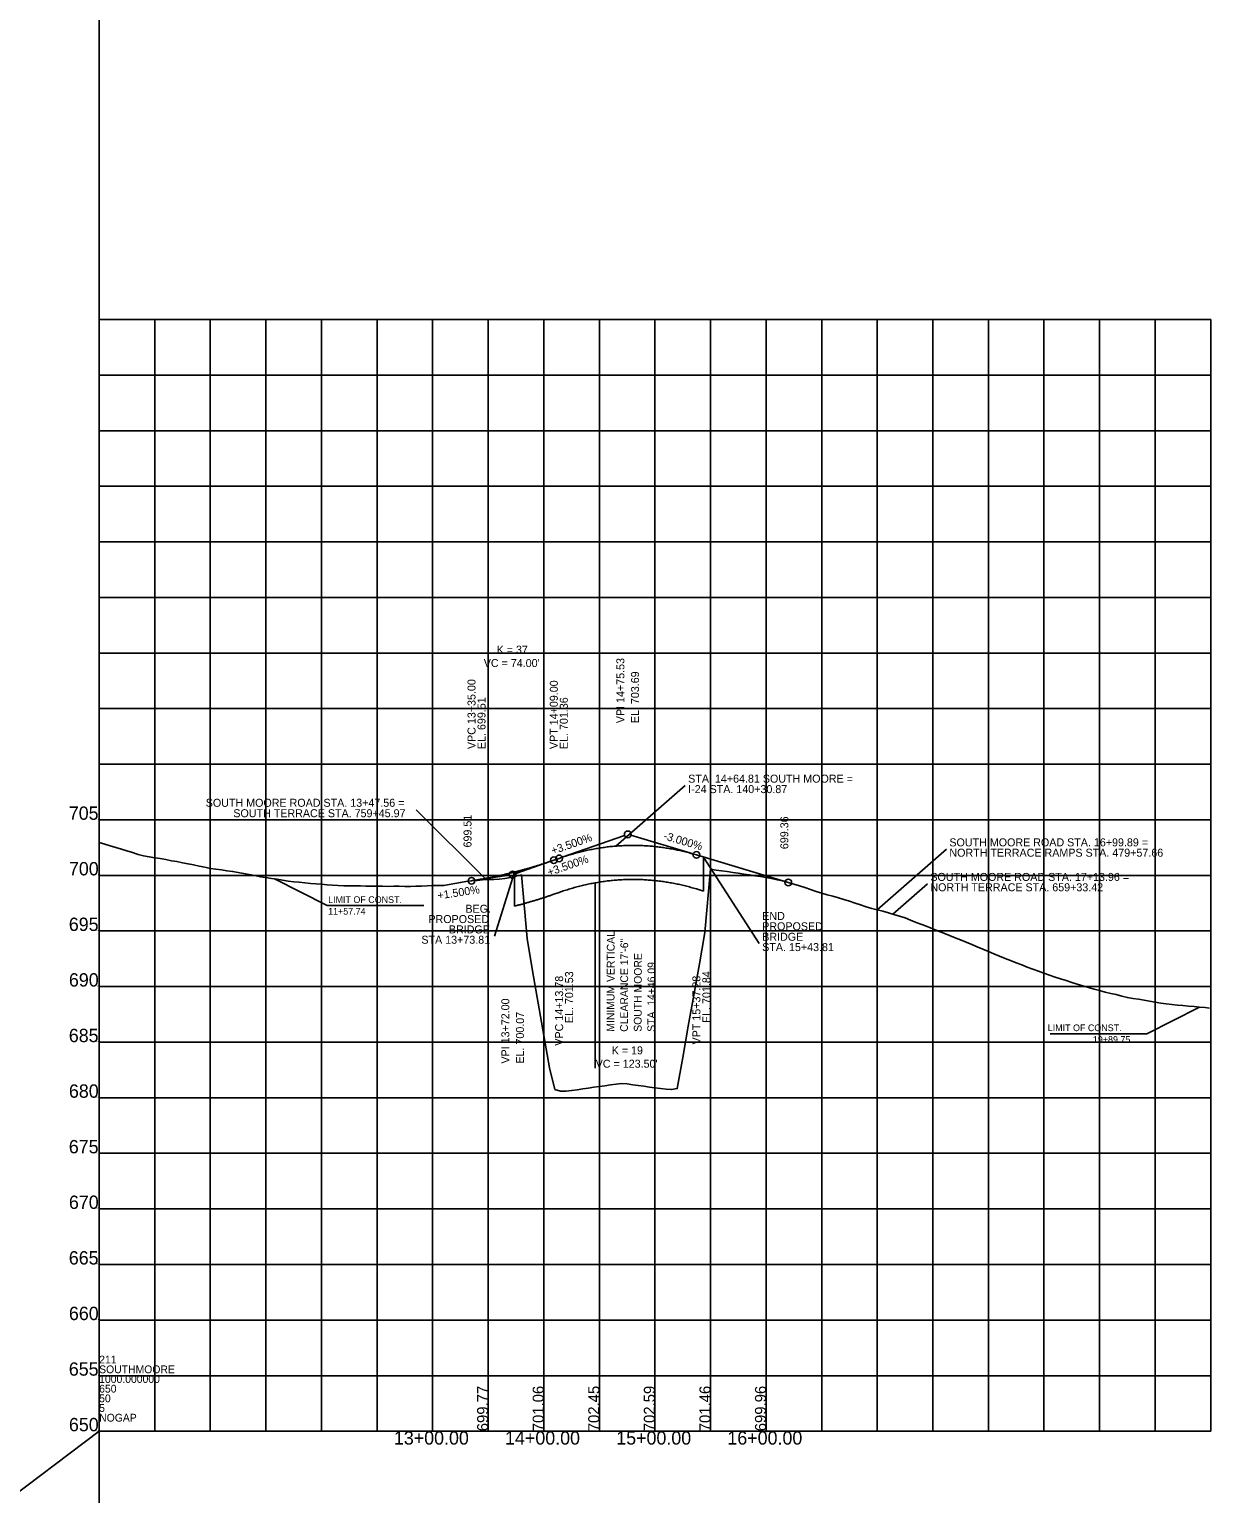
# Model space of a CAD drawing. Extents: x -7164 to 2214450, y -19642 to 253469.
# Drawn here: x -63 to 1000, y -6056 to -4739 of the extents above; entities that cross this region are included whole.
import ezdxf

# ---------------------------------------------------------------- set-up
doc = ezdxf.new("R2010")
doc.units = 0
for name, color, linetype in [('DESIGN - PROFILE - Proposed', 7, 'Continuous'), ('DESIGN - PROFILE - Proposed Curve Text', 7, 'Continuous'), ('DESIGN - PROFILE - Proposed Text', 7, 'Continuous'), ('DESIGN - SCRATCH - User 1', 7, 'Continuous'), ('DESIGN - SHEET - Light Grid', 7, 'Continuous'), ('SURVEY - PROFILE - Ground Line with Text', 7, 'Continuous')]:
    doc.layers.add(name, color=color, linetype=linetype)

msp = doc.modelspace()

# ---------------------------------------------------------------- linework, layer by layer
at = {"layer": 'DESIGN - PROFILE - Proposed'}
for p, q in [((409, -5486.4), (413.8, -5484.7)), ((537.3, -5481.6), (620, -5506.4)), ((543.8, -5483.6), (543.8, -5514.2)), ((373.8, -5497), (373.8, -5527.6)), ((409, -5517), (413.8, -5515.3)), ((537.3, -5512.2), (543.8, -5514.2)), ((292, -5527.1), (205, -5527.1)), ((855.5, -5642.4), (942.5, -5642.4))]:
    msp.add_line(p, q, dxfattribs=at)
for points in [[(205, -5527.1), (157.7, -5503.1)], [(942.5, -5642.4), (989.8, -5618.4)]]:
    msp.add_lwpolyline(points, dxfattribs=at)
for points in [[(413.8, -5484.7), (416.3, -5483.8), (418.7, -5483), (421.2, -5482.2), (423.7, -5481.5), (426.1, -5480.8), (428.6, -5480.1), (431.1, -5479.4), (433.5, -5478.8), (436, -5478.2), (438.5, -5477.6), (441, -5477.1), (443.4, -5476.6), (445.9, -5476.2), (448.4, -5475.7), (450.8, -5475.3), (453.3, -5475), (455.8, -5474.6), (458.2, -5474.3), (460.7, -5474), (463.2, -5473.8), (465.7, -5473.6), (468.1, -5473.4), (470.6, -5473.3), (473.1, -5473.2), (475.5, -5473.1), (478, -5473.1), (480.5, -5473), (482.9, -5473.1), (485.4, -5473.1), (487.9, -5473.2), (490.3, -5473.3), (492.8, -5473.5), (495.3, -5473.6), (497.8, -5473.8), (500.2, -5474.1), (502.7, -5474.4), (505.2, -5474.7), (507.6, -5475), (510.1, -5475.4), (512.6, -5475.8), (515, -5476.2), (517.5, -5476.7), (520, -5477.2), (522.5, -5477.7), (524.9, -5478.3), (527.4, -5478.9), (529.9, -5479.5), (532.3, -5480.2), (534.8, -5480.9), (537.3, -5481.6)], [(335, -5504.9), (336.5, -5504.6), (338, -5504.4), (339.4, -5504.2), (340.9, -5503.9), (342.4, -5503.7), (343.9, -5503.4), (345.4, -5503.2), (346.8, -5502.9), (348.3, -5502.6), (349.8, -5502.3), (351.3, -5502.1), (352.8, -5501.8), (354.2, -5501.5), (355.7, -5501.2), (357.2, -5500.9), (358.7, -5500.5), (360.2, -5500.2), (361.6, -5499.9), (363.1, -5499.6), (364.6, -5499.2), (366.1, -5498.9), (367.6, -5498.5), (369, -5498.2), (370.5, -5497.8), (372, -5497.5), (373.5, -5497.1), (375, -5496.7), (376.4, -5496.3), (377.9, -5495.9), (379.4, -5495.5), (380.9, -5495.1), (382.4, -5494.7), (383.8, -5494.3), (385.3, -5493.9), (386.8, -5493.5), (388.3, -5493), (389.8, -5492.6), (391.2, -5492.1), (392.7, -5491.7), (394.2, -5491.2), (395.7, -5490.8), (397.2, -5490.3), (398.6, -5489.8), (400.1, -5489.4), (401.6, -5488.9), (403.1, -5488.4), (404.6, -5487.9), (406, -5487.4), (407.5, -5486.9), (409, -5486.4)], [(413.8, -5515.3), (416.3, -5514.5), (418.7, -5513.6), (421.2, -5512.9), (423.7, -5512.1), (426.1, -5511.4), (428.6, -5510.7), (431.1, -5510), (433.5, -5509.4), (436, -5508.8), (438.5, -5508.3), (441, -5507.7), (443.4, -5507.2), (445.9, -5506.8), (448.4, -5506.3), (450.8, -5505.9), (453.3, -5505.6), (455.8, -5505.2), (458.2, -5504.9), (460.7, -5504.7), (463.2, -5504.4), (465.7, -5504.2), (468.1, -5504.1), (470.6, -5503.9), (473.1, -5503.8), (475.5, -5503.7), (478, -5503.7), (480.5, -5503.7), (482.9, -5503.7), (485.4, -5503.7), (487.9, -5503.8), (490.3, -5503.9), (492.8, -5504.1), (495.3, -5504.3), (497.8, -5504.5), (500.2, -5504.7), (502.7, -5505), (505.2, -5505.3), (507.6, -5505.6), (510.1, -5506), (512.6, -5506.4), (515, -5506.8), (517.5, -5507.3), (520, -5507.8), (522.5, -5508.3), (524.9, -5508.9), (527.4, -5509.5), (529.9, -5510.1), (532.3, -5510.8), (534.8, -5511.5), (537.3, -5512.2)], [(373.8, -5527.6), (375, -5527.3), (376.4, -5526.9), (377.9, -5526.5), (379.4, -5526.2), (380.9, -5525.8), (382.4, -5525.3), (383.8, -5524.9), (385.3, -5524.5), (386.8, -5524.1), (388.3, -5523.6), (389.8, -5523.2), (391.2, -5522.8), (392.7, -5522.3), (394.2, -5521.9), (395.7, -5521.4), (397.2, -5520.9), (398.6, -5520.5), (400.1, -5520), (401.6, -5519.5), (403.1, -5519), (404.6, -5518.5), (406, -5518), (407.5, -5517.5), (409, -5517)]]:
    msp.add_spline(points, degree=3, dxfattribs=at)
at = {"layer": 'DESIGN - PROFILE - Proposed Text'}
for p, q in [((464.8, -5473.7), (527.2, -5419.2)), ((347.6, -5503), (285.2, -5440.9)), ((416.6, -5483.7), (472.7, -5464.1)), ((534.4, -5480.7), (478.4, -5463.9)), ((699.9, -5530.9), (762.3, -5476.4)), ((406.2, -5487.3), (374.8, -5498.3)), ((543.8, -5483.6), (593.8, -5561.3)), ((338, -5504.4), (369, -5499.7)), ((373.8, -5497), (355.8, -5554.8)), ((446.1, -5673.4), (446.1, -5506.7)), ((714, -5534.8), (745.2, -5507.5))]:
    msp.add_line(p, q, dxfattribs=at)
for centre in [(475.5, -5463.1), (537.3, -5481.6), (409, -5486.4), (413.8, -5484.7), (335, -5504.9), (335, -5504.9), (372, -5499.3), (620, -5506.4)]:
    msp.add_circle(centre, 3, dxfattribs=at)
at = {"layer": 'DESIGN - SCRATCH - User 1'}
for p, q in [((1000, -5000), (0, -5000)), ((0, -5000), (0, -6000)), ((1000, -5000), (0, -5000)), ((0, -5000), (0, -6000)), ((1000, -6000), (1000, -5000)), ((1000, -6000), (1000, -5000)), ((0, -6000), (-6163.5, -10642.5)), ((0, -6000), (-6163.5, -10642.5)), ((0, -6000), (1000, -6000)), ((0, -6000), (1000, -6000))]:
    msp.add_line(p, q, dxfattribs=at)
at = {"layer": 'DESIGN - SHEET - Light Grid'}
for p, q in [((0, -6000), (0, -3500)), ((0, -6000), (0, -3500)), ((50, -6000), (50, -5000)), ((50, -6000), (50, -5000)), ((100, -6000), (100, -5000)), ((100, -6000), (100, -5000)), ((150, -6000), (150, -5000)), ((150, -6000), (150, -5000)), ((200, -6000), (200, -5000)), ((200, -6000), (200, -5000)), ((250, -6000), (250, -5000)), ((250, -6000), (250, -5000)), ((300, -6000), (300, -5000)), ((300, -6000), (300, -5000)), ((350, -6000), (350, -5000)), ((350, -6000), (350, -5000)), ((400, -6000), (400, -5000)), ((400, -6000), (400, -5000)), ((450, -6000), (450, -5000)), ((450, -6000), (450, -5000)), ((500, -6000), (500, -5000)), ((500, -6000), (500, -5000)), ((550, -6000), (550, -5000)), ((550, -6000), (550, -5000)), ((600, -6000), (600, -5000)), ((600, -6000), (600, -5000)), ((650, -6000), (650, -5000)), ((650, -6000), (650, -5000)), ((700, -6000), (700, -5000)), ((700, -6000), (700, -5000)), ((750, -6000), (750, -5000)), ((750, -6000), (750, -5000)), ((800, -6000), (800, -5000)), ((800, -6000), (800, -5000)), ((850, -6000), (850, -5000)), ((850, -6000), (850, -5000)), ((900, -6000), (900, -5000)), ((900, -6000), (900, -5000)), ((950, -6000), (950, -5000)), ((950, -6000), (950, -5000)), ((0, -5050), (1000, -5050)), ((0, -5050), (1000, -5050)), ((0, -5100), (1000, -5100)), ((0, -5100), (1000, -5100)), ((0, -5150), (1000, -5150)), ((0, -5150), (1000, -5150)), ((0, -5200), (1000, -5200)), ((0, -5200), (1000, -5200)), ((0, -5250), (1000, -5250)), ((0, -5250), (1000, -5250)), ((0, -5300), (1000, -5300)), ((0, -5300), (1000, -5300)), ((0, -5350), (1000, -5350)), ((0, -5350), (1000, -5350)), ((0, -5400), (1000, -5400)), ((0, -5400), (1000, -5400)), ((0, -5450), (1000, -5450)), ((0, -5450), (1000, -5450)), ((0, -5500), (1000, -5500)), ((0, -5500), (1000, -5500)), ((0, -5550), (1000, -5550)), ((0, -5550), (1000, -5550)), ((0, -5600), (1000, -5600)), ((0, -5600), (1000, -5600)), ((0, -5650), (1000, -5650)), ((0, -5650), (1000, -5650)), ((0, -5700), (1000, -5700)), ((0, -5700), (1000, -5700)), ((0, -5750), (1000, -5750)), ((0, -5750), (1000, -5750)), ((0, -5800), (1000, -5800)), ((0, -5800), (1000, -5800)), ((0, -5850), (1000, -5850)), ((0, -5850), (1000, -5850)), ((0, -5900), (1000, -5900)), ((0, -5900), (1000, -5900)), ((0, -5950), (1000, -5950)), ((0, -5950), (1000, -5950)), ((0, -6000), (1000, -6000)), ((0, -6000), (0, -8500)), ((0, -6000), (1000, -6000)), ((0, -6000), (0, -8500))]:
    msp.add_line(p, q, dxfattribs=at)
at = {"layer": 'SURVEY - PROFILE - Ground Line with Text'}
for points in [[(0, -5470.3), (5, -5471.9), (10, -5473.5), (15, -5475), (20, -5476.5), (25, -5478), (30, -5479.5), (35, -5481.2), (40, -5482.4), (45, -5483.2), (50, -5484.1), (55, -5484.9), (60, -5485.8), (65, -5486.8), (70, -5487.6), (75, -5488.7), (80, -5489.7), (85, -5490.6), (90, -5491.7), (95, -5492.7), (100, -5493.7), (105, -5494.4), (110, -5495.1), (115, -5495.8), (120, -5496.5), (125, -5497.4), (130, -5498.2), (135, -5499.2), (140, -5500.2), (145, -5501.2), (150, -5501.9), (155, -5502.7), (160, -5503.5), (165, -5504.3), (170, -5505.1), (175, -5505.7), (180, -5506.2), (185, -5506.8), (190, -5507.3), (195, -5507.6), (200, -5508), (205, -5508.5), (210, -5508.9), (215, -5509.2), (220, -5509.3), (225, -5509.4), (230, -5509.4), (235, -5509.5), (240, -5509.6), (245, -5509.6), (250, -5509.7), (255, -5509.8), (260, -5509.9), (265, -5509.8), (270, -5509.8), (275, -5509.9), (280, -5509.9), (285, -5509.8), (290, -5509.6), (295, -5509.3), (300, -5509.2), (305, -5509), (310, -5509.2), (315, -5508.2), (320, -5507.2), (325, -5506.3), (330, -5505.6), (335, -5504.9), (340, -5504.5), (345, -5504.1), (350, -5503.8), (355, -5503.6), (360, -5503.3), (365, -5502.8), (370, -5501.9), (375, -5500.8), (380, -5499.6), (385, -5556.8), (390, -5585.8), (395, -5614.8), (400, -5643.9), (405, -5673), (410, -5692.5), (415, -5694), (420, -5694.1), (425, -5693.5), (430, -5692.8), (435, -5692.1), (440, -5691.3), (445, -5690.6), (450, -5689.9), (455, -5689.3), (460, -5688.5), (465, -5687.7), (470, -5687.2), (475, -5687.6), (480, -5688.3), (485, -5689), (490, -5689.7), (495, -5690.4), (500, -5691)], [(0, -5470.3), (5, -5471.9), (10, -5473.5), (15, -5475), (20, -5476.5), (25, -5478), (30, -5479.5), (35, -5481.2), (40, -5482.4), (45, -5483.2), (50, -5484.1), (55, -5484.9), (60, -5485.8), (65, -5486.8), (70, -5487.6), (75, -5488.7), (80, -5489.7), (85, -5490.6), (90, -5491.7), (95, -5492.7), (100, -5493.7), (105, -5494.4), (110, -5495.1), (115, -5495.8), (120, -5496.5), (125, -5497.4), (130, -5498.2), (135, -5499.2), (140, -5500.2), (145, -5501.2), (150, -5501.9), (155, -5502.7), (160, -5503.5), (165, -5504.3), (170, -5505.1), (175, -5505.7), (180, -5506.2), (185, -5506.8), (190, -5507.3), (195, -5507.6), (200, -5508), (205, -5508.5), (210, -5508.9), (215, -5509.2), (220, -5509.3), (225, -5509.4), (230, -5509.4), (235, -5509.5), (240, -5509.6), (245, -5509.6), (250, -5509.7), (255, -5509.8), (260, -5509.9), (265, -5509.8), (270, -5509.8), (275, -5509.9), (280, -5509.9), (285, -5509.8), (290, -5509.6), (295, -5509.3), (300, -5509.2), (305, -5509), (310, -5509.2), (315, -5508.2), (320, -5507.2), (325, -5506.3), (330, -5505.6), (335, -5504.9), (340, -5504.5), (345, -5504.1), (350, -5503.8), (355, -5503.6), (360, -5503.3), (365, -5502.8), (370, -5501.9), (375, -5500.8), (380, -5499.6), (385, -5556.8), (390, -5585.8), (395, -5614.8), (400, -5643.9), (405, -5673), (410, -5692.5), (415, -5694), (420, -5694.1), (425, -5693.5), (430, -5692.8), (435, -5692.1), (440, -5691.3), (445, -5690.6), (450, -5689.9), (455, -5689.3), (460, -5688.5), (465, -5687.7), (470, -5687.2), (475, -5687.6), (480, -5688.3), (485, -5689), (490, -5689.7), (495, -5690.4), (500, -5691)], [(500, -5691), (505, -5691.6), (510, -5692.2), (515, -5692.7), (520, -5691.7), (525, -5663.7), (530, -5635.7), (535, -5607.7), (540, -5579.5), (545, -5551.3), (550, -5494.4), (555, -5495.2), (560, -5495.9), (565, -5496.6), (570, -5497.4), (575, -5498.1), (580, -5498.8), (585, -5499.6), (590, -5500.3), (595, -5501.1), (600, -5501.8), (605, -5502.8), (610, -5503.9), (615, -5505), (620, -5506.4), (625, -5507.9), (630, -5509.3), (635, -5510.8), (640, -5512.6), (645, -5514.4), (650, -5515.9), (655, -5517.4), (660, -5518.8), (665, -5520.3), (670, -5521.8), (675, -5523.3), (680, -5524.9), (685, -5526.5), (690, -5528.3), (695, -5529.9), (700, -5530.9), (705, -5532.2), (710, -5533.6), (715, -5535.1), (720, -5536.7), (725, -5538.2), (730, -5540.3), (735, -5542.4), (740, -5544.1), (745, -5546.1), (750, -5548.2), (755, -5550.1), (760, -5552.1), (765, -5554.1), (770, -5556.1), (775, -5558.1), (780, -5560.1), (785, -5562.1), (790, -5564.2), (795, -5566.3), (800, -5568.4), (805, -5570.5), (810, -5572.6), (815, -5574.7), (820, -5576.7), (825, -5578.6), (830, -5580.6), (835, -5582.5), (840, -5584.3), (845, -5586.1), (850, -5588), (855, -5589.8), (860, -5591.5), (865, -5593.2), (870, -5594.7), (875, -5596.3), (880, -5597.9), (885, -5599.4), (890, -5600.9), (895, -5602.3), (900, -5603.6), (905, -5604.9), (910, -5606.1), (915, -5607.2), (920, -5608.6), (925, -5609.9), (930, -5610.6), (935, -5611.3), (940, -5612.2), (945, -5613.1), (950, -5614), (955, -5614.8), (960, -5615.5), (965, -5616.1), (970, -5616.6), (975, -5617.1), (980, -5617.5), (985, -5618), (990, -5618.5), (995, -5618.9), (999, -5619.4)], [(500, -5691), (505, -5691.6), (510, -5692.2), (515, -5692.7), (520, -5691.7), (525, -5663.7), (530, -5635.7), (535, -5607.7), (540, -5579.5), (545, -5551.3), (550, -5494.4), (555, -5495.2), (560, -5495.9), (565, -5496.6), (570, -5497.4), (575, -5498.1), (580, -5498.8), (585, -5499.6), (590, -5500.3), (595, -5501.1), (600, -5501.8), (605, -5502.8), (610, -5503.9), (615, -5505), (620, -5506.4), (625, -5507.9), (630, -5509.3), (635, -5510.8), (640, -5512.6), (645, -5514.4), (650, -5515.9), (655, -5517.4), (660, -5518.8), (665, -5520.3), (670, -5521.8), (675, -5523.3), (680, -5524.9), (685, -5526.5), (690, -5528.3), (695, -5529.9), (700, -5530.9), (705, -5532.2), (710, -5533.6), (715, -5535.1), (720, -5536.7), (725, -5538.2), (730, -5540.3), (735, -5542.4), (740, -5544.1), (745, -5546.1), (750, -5548.2), (755, -5550.1), (760, -5552.1), (765, -5554.1), (770, -5556.1), (775, -5558.1), (780, -5560.1), (785, -5562.1), (790, -5564.2), (795, -5566.3), (800, -5568.4), (805, -5570.5), (810, -5572.6), (815, -5574.7), (820, -5576.7), (825, -5578.6), (830, -5580.6), (835, -5582.5), (840, -5584.3), (845, -5586.1), (850, -5588), (855, -5589.8), (860, -5591.5), (865, -5593.2), (870, -5594.7), (875, -5596.3), (880, -5597.9), (885, -5599.4), (890, -5600.9), (895, -5602.3), (900, -5603.6), (905, -5604.9), (910, -5606.1), (915, -5607.2), (920, -5608.6), (925, -5609.9), (930, -5610.6), (935, -5611.3), (940, -5612.2), (945, -5613.1), (950, -5614), (955, -5614.8), (960, -5615.5), (965, -5616.1), (970, -5616.6), (975, -5617.1), (980, -5617.5), (985, -5618), (990, -5618.5), (995, -5618.9), (999, -5619.4)]]:
    msp.add_lwpolyline(points, dxfattribs=at)

# ---------------------------------------------------------------- texts
at = {"layer": 'DESIGN - PROFILE - Proposed'}
for s, p in [('LIMIT OF CONST.', (206, -5524.8)), ('11+57.74', (206, -5535.3)), ('LIMIT OF CONST.', (853.4, -5640.1)), ('19+89.75', (894, -5650.6))]:
    msp.add_text(s, height=6, dxfattribs=at).set_placement(p)
at = {"layer": 'DESIGN - PROFILE - Proposed Curve Text'}
for s, p in [('K = 37', (357.6, -5300.6)), ("VC = 74.00'", (346, -5312.6)), ('SOUTH MOORE ROAD STA. 13+47.56 =', (95.9, -5438.3)), ('SOUTH TERRACE STA. 759+45.97', (120.7, -5447.7)), ('BEG. ', (329.5, -5533.6)), ('PROPOSED', (296.2, -5542.9)), ('BRIDGE', (314.6, -5552.2)), ('STA 13+73.81', (289.9, -5561.5)), ('K = 19', (461.1, -5661)), ("VC = 123.50'", (446.7, -5673))]:
    msp.add_text(s, height=7.2, dxfattribs=at).set_placement(p)
for s, rotation, p in [('VPI 14+75.53', 90, (472.5, -5363.1)), ('EL. 703.69', 90, (485.7, -5363.1)), ('STA. 14+64.81 SOUTH MOORE =', 360, (529.9, -5416.6)), ('I-24 STA. 140+30.87', 360, (529.9, -5426)), ('699.51', 90, (335, -5474.9)), ('699.36', 90, (620, -5476.4)), ('SOUTH MOORE ROAD STA. 16+99.89 =', 360, (764.9, -5473.9)), ('NORTH TERRACE RAMPS STA. 479+57.66', 360, (764.9, -5483.2)), ('SOUTH MOORE ROAD STA. 17+13.96 =', 360, (747.8, -5505)), ('NORTH TERRACE STA. 659+33.42', 360, (747.8, -5514.3)), ('END ', 360, (596.5, -5540.1)), ('PROPOSED ', 360, (596.5, -5549.4)), ('BRIDGE', 360, (596.5, -5558.8)), ('STA. 15+43.81', 360, (596.5, -5568.1)), ('VPI 13+72.00', 90, (369, -5669.3)), ('EL. 700.07', 90, (382.2, -5669.3))]:
    msp.add_text(s, height=7.2, rotation=rotation, dxfattribs=at).set_placement(p)
at = {"layer": 'DESIGN - PROFILE - Proposed Text'}
for s, height, rotation, p in [('VPC 13+35.00 ', 7.2, 90, (338.6, -5386.4)), ('VPT 14+09.00 ', 7.2, 90, (412.6, -5386.4)), ('EL. 699.51', 7.2, 90, (347.6, -5386.4)), ('EL. 701.36', 7.2, 90, (421.6, -5386.4)), ('+3.500%', 7.2, 19.2898, (408.1, -5481.4)), ('-3.000%', 7.2, 343.3006, (507.2, -5467.4)), ('+3.500%', 7.2, 19.2898, (404.7, -5500.8)), ('+1.500%', 7.2, 8.5308, (304.9, -5521.7)), ('VPC 14+13.78 ', 7.2, 90, (417.4, -5653.2)), ('EL. 701.53', 7.2, 90, (426.4, -5632.9)), ('VPT 15+37.28 ', 7.2, 90, (540.9, -5652.1)), ('EL. 701.84', 7.2, 90, (549.9, -5632.8)), ('699.77', 10, 90, (350, -6000)), ('701.06', 10, 90, (400, -6000)), ('702.45', 10, 90, (450, -6000)), ('702.59', 10, 90, (500, -6000)), ('701.46', 10, 90, (550, -6000)), ('699.96', 10, 90, (600, -6000))]:
    msp.add_text(s, height=height, rotation=rotation, dxfattribs=at).set_placement(p)
for s, height, p in [('705', 12, (-27.3, -5450)), ('705', 1, (-2.3, -5450)), ('700', 12, (-27.2, -5500)), ('700', 1, (-2.3, -5500)), ('695', 12, (-27.3, -5550)), ('695', 1, (-2.3, -5550)), ('690', 12, (-27.2, -5600)), ('690', 1, (-2.3, -5600)), ('685', 12, (-27.3, -5650)), ('685', 1, (-2.3, -5650)), ('680', 12, (-27.2, -5700)), ('680', 1, (-2.3, -5700)), ('675', 12, (-27.3, -5750)), ('675', 1, (-2.3, -5750)), ('670', 12, (-27.2, -5800)), ('670', 1, (-2.3, -5800)), ('665', 12, (-27.3, -5850)), ('665', 1, (-2.3, -5850)), ('660', 12, (-27.2, -5900)), ('660', 1, (-2.3, -5900)), ('655', 12, (-27.3, -5950)), ('655', 1, (-2.3, -5950)), ('650', 12, (-27.2, -6000)), ('650', 1, (-2.3, -6000)), ('13+00.00', 12, (265.2, -6012)), ('14+00.00', 12, (365.2, -6012)), ('14+00.00', 1, (397.1, -6001)), ('15+00.00', 12, (465.2, -6012)), ('15+00.00', 1, (497.1, -6001)), ('16+00.00', 12, (565.2, -6012)), ('16+00.00', 1, (597.1, -6001))]:
    msp.add_text(s, height=height, dxfattribs=at).set_placement(p)
at = {"layer": 'DESIGN - SHEET - Light Grid'}
for s, p in [('211', (0, -5939)), ('211', (0, -5939)), ('SOUTHMOORE', (0, -5947.8)), ('SOUTHMOORE', (0, -5947.8)), ('1000.000000', (0, -5956.5)), ('1000.000000', (0, -5956.5)), ('50', (0, -5973.9)), ('50', (0, -5973.9)), ('650', (0, -5965.2)), ('650', (0, -5965.2)), ('5', (0, -5982.6)), ('5', (0, -5982.6)), ('NOGAP', (0, -5991.3)), ('NOGAP', (0, -5991.3))]:
    msp.add_text(s, height=7, dxfattribs=at).set_placement(p)
at = {"layer": 'SURVEY - PROFILE - Ground Line with Text'}
for s, p in [('MINIMUM VERTICAL', (463.5, -5640.6)), ('CLEARANCE 17\'-6"', (475.7, -5640.7)), ('SOUTH MOORE ', (488, -5640.7)), ('STA. 14+46.09', (500.2, -5640.7))]:
    msp.add_text(s, height=7, rotation=89.8304, dxfattribs=at).set_placement(p)

doc.saveas('drawing.dxf')
